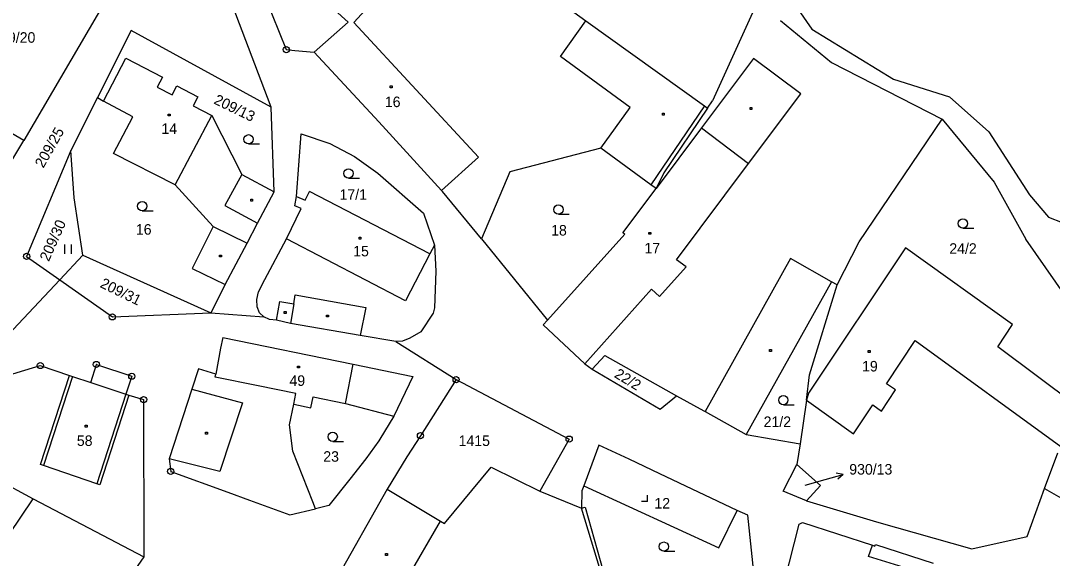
# Model space of a CAD drawing. Extents: x -796130 to -793145, y -1109506 to -1106267.
# Drawn here: x -794664.8 to -794498.3, y -1107589.9 to -1107503 of the extents above; entities that cross this region are included whole.
import ezdxf

# ---------------------------------------------------------------- set-up
doc = ezdxf.new("R2010")
doc.units = 0
for name, color, linetype in [('Komunikace', 7, 'Continuous'), ('Vrstva 1', 7, 'Continuous'), ('Vrstva 14', 7, 'Continuous'), ('Vrstva 15', 7, 'Continuous'), ('Vrstva 16', 7, 'Continuous'), ('Vrstva 2', 7, 'Continuous'), ('Vrstva 23', 7, 'Continuous'), ('Vrstva 25', 7, 'Continuous'), ('Vrstva 28', 7, 'Continuous')]:
    doc.layers.add(name, color=color, linetype=linetype)

msp = doc.modelspace()

# ---------------------------------------------------------------- linework, layer by layer
at = {"layer": 'Komunikace'}
msp.add_line((-794538.21, -1107578.04), (-794534.98, -1107577.13), dxfattribs=at)
at = {"layer": 'Vrstva 1'}
for p, q in [((-794638.89, -1107478.74), (-794664.34, -1107522.36)), ((-794624.38, -1107516.97), (-794638.89, -1107478.74)), ((-794596.1, -1107486.77), (-794573.59, -1107503.03)), ((-794543.65, -1107494.87), (-794537.14, -1107504.4)), ((-794612, -1107503.26), (-794619.66, -1107496.23)), ((-794625.83, -1107498.17), (-794621.96, -1107507.68)), ((-794545.65, -1107499.33), (-794553.18, -1107515.98)), ((-794617.49, -1107508.08), (-794612, -1107503.26)), ((-794573.59, -1107503.03), (-794554.44, -1107516.79)), ((-794542.21, -1107502.97), (-794533.94, -1107509.79)), ((-794646.98, -1107504.62), (-794652.42, -1107515.42)), ((-794624.38, -1107516.97), (-794646.98, -1107504.62)), ((-794537.14, -1107504.4), (-794523.94, -1107512.44)), ((-794651.49, -1107515.99), (-794647.88, -1107509.06)), ((-794647.88, -1107509.06), (-794641.94, -1107512.11)), ((-794621.96, -1107507.68), (-794620.56, -1107507.81)), ((-794620.56, -1107507.81), (-794617.49, -1107508.08)), ((-794607.04, -1107519.35), (-794617.49, -1107508.08)), ((-794533.94, -1107509.79), (-794516.08, -1107518.91)), ((-794664.34, -1107522.36), (-794681.54, -1107512.28)), ((-794641.94, -1107512.11), (-794642.78, -1107513.75)), ((-794523.94, -1107512.44), (-794514.93, -1107515.3)), ((-794642.78, -1107513.75), (-794640.37, -1107514.98)), ((-794640.37, -1107514.98), (-794639.62, -1107513.55)), ((-794639.62, -1107513.55), (-794636.26, -1107515.31)), ((-794652.42, -1107515.42), (-794656.74, -1107523.99)), ((-794652.42, -1107515.42), (-794651.49, -1107515.99)), ((-794636.26, -1107515.31), (-794637.01, -1107516.74)), ((-794553.96, -1107517.14), (-794553.18, -1107515.98)), ((-794514.93, -1107515.3), (-794508.56, -1107520.97)), ((-794646.72, -1107518.52), (-794651.49, -1107515.99)), ((-794637.01, -1107516.74), (-794633.98, -1107518.34)), ((-794623.94, -1107530.65), (-794624.38, -1107516.97)), ((-794553.96, -1107517.14), (-794561.03, -1107527.59)), ((-794554.44, -1107516.79), (-794553.96, -1107517.14)), ((-794649.86, -1107524.45), (-794646.72, -1107518.52)), ((-794633.98, -1107518.34), (-794629.12, -1107527.83)), ((-794529.51, -1107538.75), (-794516.08, -1107518.91)), ((-794516.08, -1107518.91), (-794507.7, -1107529.11)), ((-794596.91, -1107530.42), (-794607.04, -1107519.35)), ((-794508.56, -1107520.97), (-794501.97, -1107531.12)), ((-794668.4, -1107529.11), (-794664.34, -1107522.36)), ((-794620.34, -1107531.41), (-794619.54, -1107521.27)), ((-794619.54, -1107521.27), (-794614.94, -1107522.84)), ((-794656.74, -1107523.99), (-794663.88, -1107541.08)), ((-794656.19, -1107531.61), (-794656.74, -1107523.99)), ((-794614.94, -1107522.84), (-794610.97, -1107524.94)), ((-794571.19, -1107523.58), (-794585.89, -1107527.45)), ((-794563.1, -1107529.51), (-794571.19, -1107523.58)), ((-794639.9, -1107529.55), (-794649.86, -1107524.45)), ((-794610.97, -1107524.94), (-794607.16, -1107527.66)), ((-794585.89, -1107527.45), (-794590.43, -1107538.26)), ((-794561.03, -1107527.59), (-794562.28, -1107530.13)), ((-794629.12, -1107527.83), (-794623.94, -1107530.65)), ((-794607.16, -1107527.66), (-794599.81, -1107534.1)), ((-794507.7, -1107529.11), (-794502.58, -1107538.28)), ((-794639.9, -1107529.55), (-794633.74, -1107536.26)), ((-794626.6, -1107535.72), (-794623.94, -1107530.65)), ((-794618.93, -1107532.02), (-794618.24, -1107530.61)), ((-794598.79, -1107540.67), (-794618.24, -1107530.61)), ((-794596.75, -1107530.59), (-794596.91, -1107530.42)), ((-794590.43, -1107538.26), (-794596.75, -1107530.59)), ((-794567.63, -1107537.28), (-794562.28, -1107530.13)), ((-794562.28, -1107530.13), (-794563.1, -1107529.51)), ((-794654.79, -1107540.86), (-794656.19, -1107531.61)), ((-794620.61, -1107532.9), (-794620.34, -1107531.41)), ((-794620.34, -1107531.41), (-794618.93, -1107532.02)), ((-794501.97, -1107531.12), (-794498.93, -1107534.73)), ((-794621.95, -1107538.25), (-794619.58, -1107533.37)), ((-794619.58, -1107533.37), (-794620.61, -1107532.9)), ((-794599.81, -1107534.1), (-794598.06, -1107539.27)), ((-794628.29, -1107538.94), (-794626.6, -1107535.72)), ((-794498.93, -1107534.73), (-794494.32, -1107536.54)), ((-794633.74, -1107536.26), (-794637.16, -1107543.02)), ((-794579.8, -1107551.36), (-794567.33, -1107537.5)), ((-794567.33, -1107537.5), (-794567.63, -1107537.28)), ((-794631.84, -1107545.63), (-794628.29, -1107538.94)), ((-794625.41, -1107544.82), (-794621.95, -1107538.25)), ((-794598.06, -1107539.27), (-794598.79, -1107540.67)), ((-794598.06, -1107539.27), (-794597.81, -1107543.46)), ((-794590.43, -1107538.26), (-794579.8, -1107551.36)), ((-794533.05, -1107545.68), (-794529.51, -1107538.75)), ((-794489.84, -1107556.63), (-794502.58, -1107538.28)), ((-794658.54, -1107544.85), (-794654.79, -1107540.86)), ((-794654.79, -1107540.86), (-794634.16, -1107550.18)), ((-794522.03, -1107539.72), (-794537.65, -1107563.2)), ((-794504.75, -1107552.11), (-794522.03, -1107539.72)), ((-794663.88, -1107541.08), (-794658.54, -1107544.85)), ((-794637.16, -1107543.02), (-794631.84, -1107545.63)), ((-794597.81, -1107543.46), (-794598.04, -1107549.37)), ((-794681.99, -1107569.82), (-794658.54, -1107544.85)), ((-794658.54, -1107544.85), (-794650.04, -1107550.85)), ((-794631.84, -1107545.63), (-794634.16, -1107550.18)), ((-794626.47, -1107546.79), (-794625.41, -1107544.82)), ((-794533.97, -1107545.18), (-794547.72, -1107569.86)), ((-794537.52, -1107560.22), (-794533.05, -1107545.68)), ((-794533.05, -1107545.68), (-794533.97, -1107545.18)), ((-794626.73, -1107548.07), (-794626.47, -1107546.79)), ((-794626.65, -1107549.24), (-794626.73, -1107548.07)), ((-794626.3, -1107550.19), (-794626.65, -1107549.24)), ((-794650.04, -1107550.85), (-794634.16, -1107550.18)), ((-794634.16, -1107550.18), (-794625.6, -1107550.85)), ((-794625.6, -1107550.85), (-794626.3, -1107550.19)), ((-794624.67, -1107551.25), (-794625.6, -1107550.85)), ((-794598.28, -1107550.25), (-794600.23, -1107553.29)), ((-794598.04, -1107549.37), (-794598.28, -1107550.25)), ((-794623.53, -1107551.38), (-794624.67, -1107551.25)), ((-794621.27, -1107551.91), (-794623.53, -1107551.38)), ((-794610.04, -1107553.84), (-794621.27, -1107551.91)), ((-794579.8, -1107551.36), (-794580.5, -1107552.13)), ((-794580.5, -1107552.13), (-794573.8, -1107558.43)), ((-794507.12, -1107555.67), (-794504.75, -1107552.11)), ((-794632.18, -1107554.21), (-794632.59, -1107555.91)), ((-794632.18, -1107554.21), (-794611.18, -1107558.48)), ((-794604.26, -1107554.84), (-794610.04, -1107553.84)), ((-794600.23, -1107553.29), (-794602.01, -1107554.29)), ((-794632.59, -1107555.91), (-794633.36, -1107560.09)), ((-794603.18, -1107554.77), (-794604.26, -1107554.84)), ((-794604.26, -1107554.84), (-794594.55, -1107560.99)), ((-794602.01, -1107554.29), (-794603.18, -1107554.77)), ((-794494.01, -1107565.49), (-794507.12, -1107555.67)), ((-794572.58, -1107559.3), (-794570.56, -1107557.1)), ((-794570.56, -1107557.1), (-794558.95, -1107563.59)), ((-794671.99, -1107561.86), (-794661.68, -1107558.71)), ((-794661.68, -1107558.71), (-794656.97, -1107560.31)), ((-794653.51, -1107561.44), (-794652.62, -1107558.54)), ((-794652.62, -1107558.54), (-794646.9, -1107560.44)), ((-794636.12, -1107559.25), (-794637.21, -1107562.51)), ((-794633.36, -1107560.09), (-794636.12, -1107559.25)), ((-794611.18, -1107558.48), (-794601.55, -1107560.46)), ((-794573.8, -1107558.43), (-794572.58, -1107559.3)), ((-794661.62, -1107574.71), (-794656.97, -1107560.31)), ((-794656.97, -1107560.31), (-794656.45, -1107560.49)), ((-794656.45, -1107560.49), (-794653.51, -1107561.44)), ((-794646.9, -1107560.44), (-794647.88, -1107563.36)), ((-794601.55, -1107560.46), (-794604.63, -1107566.91)), ((-794572.58, -1107559.3), (-794561.62, -1107565.76)), ((-794538.01, -1107564.28), (-794537.52, -1107560.22)), ((-794637.21, -1107562.51), (-794640.86, -1107573.78)), ((-794594.55, -1107560.99), (-794600.31, -1107570.05)), ((-794594.55, -1107560.99), (-794576.3, -1107570.6)), ((-794647.39, -1107563.5), (-794652.05, -1107577.97)), ((-794647.88, -1107563.36), (-794647.39, -1107563.5)), ((-794647.39, -1107563.5), (-794645, -1107564.21)), ((-794645, -1107564.21), (-794644.96, -1107589.6)), ((-794617.98, -1107565.56), (-794617.62, -1107563.79)), ((-794617.62, -1107563.79), (-794612.41, -1107564.85)), ((-794561.62, -1107565.76), (-794558.95, -1107563.59)), ((-794558.95, -1107563.59), (-794554.54, -1107566.01)), ((-794537.65, -1107563.2), (-794538.01, -1107564.28)), ((-794621.42, -1107568.3), (-794620.77, -1107564.97)), ((-794620.77, -1107564.97), (-794617.98, -1107565.56)), ((-794612.41, -1107564.85), (-794604.63, -1107566.91)), ((-794538.01, -1107564.28), (-794539.02, -1107571.35)), ((-794604.63, -1107566.91), (-794606.86, -1107570.63)), ((-794554.54, -1107566.01), (-794554.33, -1107566.13)), ((-794554.33, -1107566.13), (-794547.72, -1107569.86)), ((-794620.89, -1107572.55), (-794621.42, -1107568.3)), ((-794681.99, -1107569.82), (-794662.84, -1107580.24)), ((-794607.05, -1107570.9), (-794609.12, -1107573.77)), ((-794606.86, -1107570.63), (-794607.05, -1107570.9)), ((-794600.31, -1107570.05), (-794602.49, -1107573.45)), ((-794576.3, -1107570.6), (-794581.05, -1107579)), ((-794547.72, -1107569.86), (-794539.02, -1107571.35)), ((-794617.7, -1107580.74), (-794620.89, -1107572.55)), ((-794571.52, -1107571.55), (-794573.41, -1107576.68)), ((-794566.61, -1107573.82), (-794571.52, -1107571.55)), ((-794539.02, -1107571.35), (-794539.54, -1107574.67)), ((-794609.12, -1107573.77), (-794611.72, -1107577.09)), ((-794602.49, -1107573.45), (-794605.66, -1107578.68)), ((-794561.68, -1107576.23), (-794566.61, -1107573.82)), ((-794499.55, -1107578.55), (-794497.4, -1107572.82)), ((-794661.15, -1107574.87), (-794661.62, -1107574.71)), ((-794652.52, -1107577.81), (-794661.15, -1107574.87)), ((-794596.4, -1107584.24), (-794588.87, -1107575.12)), ((-794588.87, -1107575.12), (-794581.05, -1107579)), ((-794541.74, -1107578.99), (-794539.54, -1107574.67)), ((-794539.54, -1107574.67), (-794535.72, -1107578.09)), ((-794611.72, -1107577.09), (-794615.07, -1107581.32)), ((-794573.41, -1107576.68), (-794573.95, -1107578.15)), ((-794549.18, -1107582.1), (-794561.68, -1107576.23)), ((-794652.05, -1107577.97), (-794652.52, -1107577.81)), ((-794631.42, -1107579.18), (-794627.9, -1107580.47)), ((-794605.66, -1107578.68), (-794614.29, -1107593.93)), ((-794605.66, -1107578.68), (-794597.06, -1107583.83)), ((-794581.05, -1107579), (-794574.29, -1107581.74)), ((-794574.25, -1107578.97), (-794574.29, -1107581.74)), ((-794573.95, -1107578.15), (-794574.25, -1107578.97)), ((-794573.95, -1107578.15), (-794552.12, -1107588.16)), ((-794538.01, -1107580.55), (-794541.74, -1107578.99)), ((-794535.72, -1107578.09), (-794538.01, -1107580.55)), ((-794502.39, -1107586.3), (-794499.55, -1107578.55)), ((-794499.55, -1107578.55), (-794496.18, -1107580.49)), ((-794670.51, -1107591.63), (-794662.84, -1107580.24)), ((-794662.84, -1107580.24), (-794644.96, -1107589.6)), ((-794627.9, -1107580.47), (-794621.37, -1107582.85)), ((-794617.27, -1107581.85), (-794617.7, -1107580.74)), ((-794538.01, -1107580.55), (-794526.71, -1107583.95)), ((-794621.37, -1107582.85), (-794617.27, -1107581.85)), ((-794615.07, -1107581.32), (-794617.27, -1107581.85)), ((-794574.29, -1107581.74), (-794573.71, -1107581.57)), ((-794573.71, -1107581.57), (-794569.36, -1107597.17)), ((-794552.12, -1107588.16), (-794549.18, -1107582.1)), ((-794547.46, -1107582.9), (-794549.18, -1107582.1)), ((-794597.06, -1107583.83), (-794596.4, -1107584.24)), ((-794546.4, -1107593.16), (-794547.46, -1107582.9)), ((-794539.19, -1107584.36), (-794538.66, -1107584.07)), ((-794538.66, -1107584.07), (-794527.35, -1107587.73)), ((-794526.71, -1107583.95), (-794511.31, -1107588.34)), ((-794541.61, -1107593.99), (-794539.19, -1107584.36)), ((-794511.31, -1107588.34), (-794502.39, -1107586.3)), ((-794527.35, -1107587.73), (-794526.96, -1107587.89)), ((-794526.96, -1107587.89), (-794526.84, -1107587.61)), ((-794526.84, -1107587.61), (-794517.54, -1107590.65)), ((-794644.96, -1107589.6), (-794654.73, -1107603.72))]:
    msp.add_line(p, q, dxfattribs=at)
msp.add_lwpolyline([(-794640.86, -1107573.78), (-794640.62, -1107575.82), (-794631.42, -1107579.18)], dxfattribs=at)
at = {"layer": 'Vrstva 16'}
for p, q in [((-794534.98, -1107577.13), (-794532.091, -1107576.318)), ((-794532.091, -1107576.318), (-794533.189, -1107576.107)), ((-794532.091, -1107576.318), (-794532.919, -1107577.07))]:
    msp.add_line(p, q, dxfattribs=at)
at = {"layer": 'Vrstva 2'}
for p, q in [((-794596.1, -1107486.77), (-794611.05, -1107503.32)), ((-794611.05, -1107503.32), (-794590.93, -1107525.03)), ((-794577.72, -1107508.8), (-794573.59, -1107503.03)), ((-794566.43, -1107517.01), (-794577.72, -1107508.8)), ((-794546.56, -1107509.1), (-794554.95, -1107520.33)), ((-794538.93, -1107514.81), (-794546.56, -1107509.1)), ((-794547.34, -1107526.07), (-794538.93, -1107514.81)), ((-794571.19, -1107523.58), (-794566.43, -1107517.01)), ((-794554.44, -1107516.79), (-794563.1, -1107529.51)), ((-794639.9, -1107529.55), (-794633.98, -1107518.34)), ((-794554.95, -1107520.33), (-794562.28, -1107530.13)), ((-794554.95, -1107520.33), (-794547.34, -1107526.07)), ((-794590.93, -1107525.03), (-794596.91, -1107530.42)), ((-794558.96, -1107541.62), (-794547.34, -1107526.07)), ((-794629.12, -1107527.83), (-794631.88, -1107532.86)), ((-794631.88, -1107532.86), (-794626.6, -1107535.72)), ((-794633.74, -1107536.26), (-794628.29, -1107538.94)), ((-794602.74, -1107548.25), (-794621.95, -1107538.25)), ((-794598.79, -1107540.67), (-794602.74, -1107548.25)), ((-794557.42, -1107542.77), (-794558.96, -1107541.62)), ((-794540.56, -1107541.41), (-794554.33, -1107566.13)), ((-794533.97, -1107545.18), (-794540.56, -1107541.41)), ((-794561.7, -1107547.55), (-794557.42, -1107542.77)), ((-794620.75, -1107548.73), (-794620.51, -1107547.3)), ((-794620.51, -1107547.3), (-794609.1, -1107549.32)), ((-794573.8, -1107558.43), (-794563.03, -1107546.36)), ((-794563.03, -1107546.36), (-794561.7, -1107547.55)), ((-794623.53, -1107551.38), (-794622.99, -1107548.35)), ((-794622.99, -1107548.35), (-794620.75, -1107548.73)), ((-794620.75, -1107548.73), (-794621.27, -1107551.91)), ((-794609.1, -1107549.32), (-794610.04, -1107553.84)), ((-794525.07, -1107561.67), (-794520.44, -1107554.68)), ((-794520.44, -1107554.68), (-794496.93, -1107571.79)), ((-794612.41, -1107564.85), (-794611.18, -1107558.48)), ((-794656.45, -1107560.49), (-794661.15, -1107574.87)), ((-794633.46, -1107560.58), (-794633.36, -1107560.09)), ((-794626.52, -1107561.99), (-794633.46, -1107560.58)), ((-794653.51, -1107561.44), (-794647.88, -1107563.36)), ((-794637.21, -1107562.51), (-794629.05, -1107564.75)), ((-794620.42, -1107563.23), (-794626.52, -1107561.99)), ((-794523.62, -1107562.66), (-794525.07, -1107561.67)), ((-794647.88, -1107563.36), (-794652.52, -1107577.81)), ((-794620.77, -1107564.97), (-794620.42, -1107563.23)), ((-794525.87, -1107566.08), (-794523.62, -1107562.66)), ((-794629.05, -1107564.75), (-794632.67, -1107575.82)), ((-794538.01, -1107564.28), (-794530.41, -1107569.74)), ((-794530.41, -1107569.74), (-794527.31, -1107565.05)), ((-794527.31, -1107565.05), (-794525.87, -1107566.08)), ((-794632.67, -1107575.82), (-794640.86, -1107573.78)), ((-794569.61, -1107597.2), (-794574.29, -1107581.74)), ((-794602.51, -1107593.23), (-794597.06, -1107583.83)), ((-794528, -1107589.55), (-794527.35, -1107587.73)), ((-794518.17, -1107592.56), (-794528, -1107589.55))]:
    msp.add_line(p, q, dxfattribs=at)
at = {"layer": 'Vrstva 23'}
for p, q in [((-794628.05, -1107522.92), (-794626.3, -1107522.92)), ((-794611.92, -1107528.43), (-794610.17, -1107528.43)), ((-794645.21, -1107533.72), (-794643.46, -1107533.72)), ((-794578.04, -1107534.27), (-794576.29, -1107534.27)), ((-794512.74, -1107536.52), (-794510.99, -1107536.52)), ((-794657.69, -1107540.67), (-794657.69, -1107539.17)), ((-794656.69, -1107539.17), (-794656.69, -1107540.67)), ((-794541.73, -1107565.05), (-794539.98, -1107565.05)), ((-794614.47, -1107570.97), (-794612.72, -1107570.97)), ((-794563.64, -1107580.66), (-794564.64, -1107580.66)), ((-794563.64, -1107580.66), (-794563.64, -1107579.66)), ((-794561.02, -1107588.71), (-794559.27, -1107588.71))]:
    msp.add_line(p, q, dxfattribs=at)
for centre in [(-794628.05, -1107522.17), (-794611.92, -1107527.68), (-794645.21, -1107532.97), (-794578.04, -1107533.52), (-794512.74, -1107535.77), (-794541.73, -1107564.3), (-794614.47, -1107570.22), (-794561.02, -1107587.96)]:
    msp.add_circle(centre, 0.75, dxfattribs=at)
at = {"layer": 'Vrstva 25'}
for p, q in [((-794605.19, -1107513.56), (-794604.89, -1107513.56)), ((-794605.19, -1107513.86), (-794605.19, -1107513.56)), ((-794604.89, -1107513.86), (-794605.19, -1107513.86)), ((-794604.89, -1107513.56), (-794604.89, -1107513.86)), ((-794547.1, -1107517.03), (-794546.8, -1107517.03)), ((-794547.1, -1107517.33), (-794547.1, -1107517.03)), ((-794546.8, -1107517.33), (-794547.1, -1107517.33)), ((-794546.8, -1107517.03), (-794546.8, -1107517.33)), ((-794641.02, -1107518.09), (-794640.72, -1107518.09)), ((-794641.02, -1107518.39), (-794641.02, -1107518.09)), ((-794640.72, -1107518.39), (-794641.02, -1107518.39)), ((-794640.72, -1107518.09), (-794640.72, -1107518.39)), ((-794561.26, -1107517.97), (-794560.96, -1107517.97)), ((-794561.26, -1107518.27), (-794561.26, -1107517.97)), ((-794560.96, -1107518.27), (-794561.26, -1107518.27)), ((-794560.96, -1107517.97), (-794560.96, -1107518.27)), ((-794627.71, -1107531.85), (-794627.41, -1107531.85)), ((-794627.71, -1107532.15), (-794627.71, -1107531.85)), ((-794627.41, -1107532.15), (-794627.71, -1107532.15)), ((-794627.41, -1107531.85), (-794627.41, -1107532.15)), ((-794563.43, -1107537.2), (-794563.13, -1107537.2)), ((-794563.43, -1107537.5), (-794563.43, -1107537.2)), ((-794563.13, -1107537.5), (-794563.43, -1107537.5)), ((-794563.13, -1107537.2), (-794563.13, -1107537.5)), ((-794610.22, -1107537.99), (-794609.92, -1107537.99)), ((-794610.22, -1107538.29), (-794610.22, -1107537.99)), ((-794609.92, -1107538.29), (-794610.22, -1107538.29)), ((-794609.92, -1107537.99), (-794609.92, -1107538.29)), ((-794632.73, -1107540.87), (-794632.43, -1107540.87)), ((-794632.73, -1107541.17), (-794632.73, -1107540.87)), ((-794632.43, -1107540.87), (-794632.43, -1107541.17)), ((-794632.43, -1107541.17), (-794632.73, -1107541.17)), ((-794622.31, -1107550), (-794622.01, -1107550)), ((-794622.31, -1107550.3), (-794622.31, -1107550)), ((-794622.01, -1107550.3), (-794622.31, -1107550.3)), ((-794622.01, -1107550), (-794622.01, -1107550.3)), ((-794615.46, -1107550.55), (-794615.16, -1107550.55)), ((-794615.46, -1107550.85), (-794615.46, -1107550.55)), ((-794615.16, -1107550.85), (-794615.46, -1107550.85)), ((-794615.16, -1107550.55), (-794615.16, -1107550.85)), ((-794543.94, -1107556.14), (-794543.64, -1107556.14)), ((-794543.94, -1107556.44), (-794543.94, -1107556.14)), ((-794543.64, -1107556.44), (-794543.94, -1107556.44)), ((-794543.64, -1107556.14), (-794543.64, -1107556.44)), ((-794528.02, -1107556.28), (-794527.72, -1107556.28)), ((-794528.02, -1107556.58), (-794528.02, -1107556.28)), ((-794527.72, -1107556.58), (-794528.02, -1107556.58)), ((-794527.72, -1107556.28), (-794527.72, -1107556.58)), ((-794620.13, -1107558.8), (-794619.83, -1107558.8)), ((-794620.13, -1107559.1), (-794620.13, -1107558.8)), ((-794619.83, -1107559.1), (-794620.13, -1107559.1)), ((-794619.83, -1107558.8), (-794619.83, -1107559.1)), ((-794654.42, -1107568.36), (-794654.12, -1107568.36)), ((-794654.42, -1107568.66), (-794654.42, -1107568.36)), ((-794654.12, -1107568.66), (-794654.42, -1107568.66)), ((-794654.12, -1107568.36), (-794654.12, -1107568.66)), ((-794635, -1107569.48), (-794634.7, -1107569.48)), ((-794635, -1107569.78), (-794635, -1107569.48)), ((-794634.7, -1107569.78), (-794635, -1107569.78)), ((-794634.7, -1107569.48), (-794634.7, -1107569.78)), ((-794605.94, -1107589.08), (-794605.64, -1107589.08)), ((-794605.94, -1107589.38), (-794605.94, -1107589.08)), ((-794605.64, -1107589.08), (-794605.64, -1107589.38)), ((-794605.64, -1107589.38), (-794605.94, -1107589.38))]:
    msp.add_line(p, q, dxfattribs=at)
at = {"layer": 'Vrstva 28'}
for centre, radius in [((-794621.96, -1107507.68), 0.5), ((-794621.96, -1107507.68), 0.01), ((-794663.88, -1107541.08), 0.5), ((-794663.88, -1107541.08), 0.01), ((-794650.04, -1107550.85), 0.5), ((-794650.04, -1107550.85), 0.01), ((-794661.68, -1107558.71), 0.5), ((-794661.68, -1107558.71), 0.01), ((-794652.62, -1107558.54), 0.5), ((-794652.62, -1107558.54), 0.01), ((-794646.9, -1107560.44), 0.5), ((-794646.9, -1107560.44), 0.01), ((-794594.55, -1107560.99), 0.5), ((-794594.55, -1107560.99), 0.01), ((-794645, -1107564.21), 0.5), ((-794645, -1107564.21), 0.01), ((-794600.31, -1107570.05), 0.5), ((-794600.31, -1107570.05), 0.01), ((-794576.3, -1107570.6), 0.5), ((-794576.3, -1107570.6), 0.01), ((-794640.62, -1107575.82), 0.5), ((-794640.62, -1107575.82), 0.01)]:
    msp.add_circle(centre, radius, dxfattribs=at)

# ---------------------------------------------------------------- texts
at = {"layer": 'Vrstva 14'}
for s, height, p in [('209/20', 1.7, (-794669.42, -1107506.57)), ('17/1', 1.7, (-794613.37, -1107531.94)), ('16', 1.7, (-794646.24, -1107537.57)), ('18', 1.7, (-794579.21, -1107537.71)), ('24/2', 1.7, (-794514.94, -1107540.66)), ('21/2', 1.7, (-794544.91, -1107568.64)), ('1415', 1.7, (-794594.145, -1107571.71)), ('23', 1.7, (-794615.99, -1107574.25)), ('930/13', 0.1, (-794538.21, -1107578.04))]:
    msp.add_text(s, height=height, dxfattribs=at).set_placement(p)
for s, rotation, p in [('209/13', 334.07865, (-794633.79, -1107516.35)), ('209/25', 60.45165, (-794661.18, -1107526.92)), ('209/30', 66.02751, (-794660.3, -1107542.01)), ('209/31', 333.8847, (-794652.16, -1107546)), ('22/2', 328.81275, (-794569.15, -1107560.52))]:
    msp.add_text(s, height=1.7, rotation=rotation, dxfattribs=at).set_placement(p)
at = {"layer": 'Vrstva 15'}
for s, p in [('16', (-794606.05, -1107516.97)), ('14', (-794642.12, -1107521.3)), ('17', (-794564.15, -1107540.6)), ('15', (-794611.16, -1107541.08)), ('19', (-794529.02, -1107559.67)), ('49', (-794621.45, -1107562)), ('58', (-794655.77, -1107571.7)), ('12', (-794562.54, -1107581.81))]:
    msp.add_text(s, height=1.7, dxfattribs=at).set_placement(p)
at = {"layer": 'Vrstva 16'}
msp.add_text('930/13', height=1.7, dxfattribs=at).set_placement((-794531.09, -1107576.32))

doc.saveas('drawing.dxf')
